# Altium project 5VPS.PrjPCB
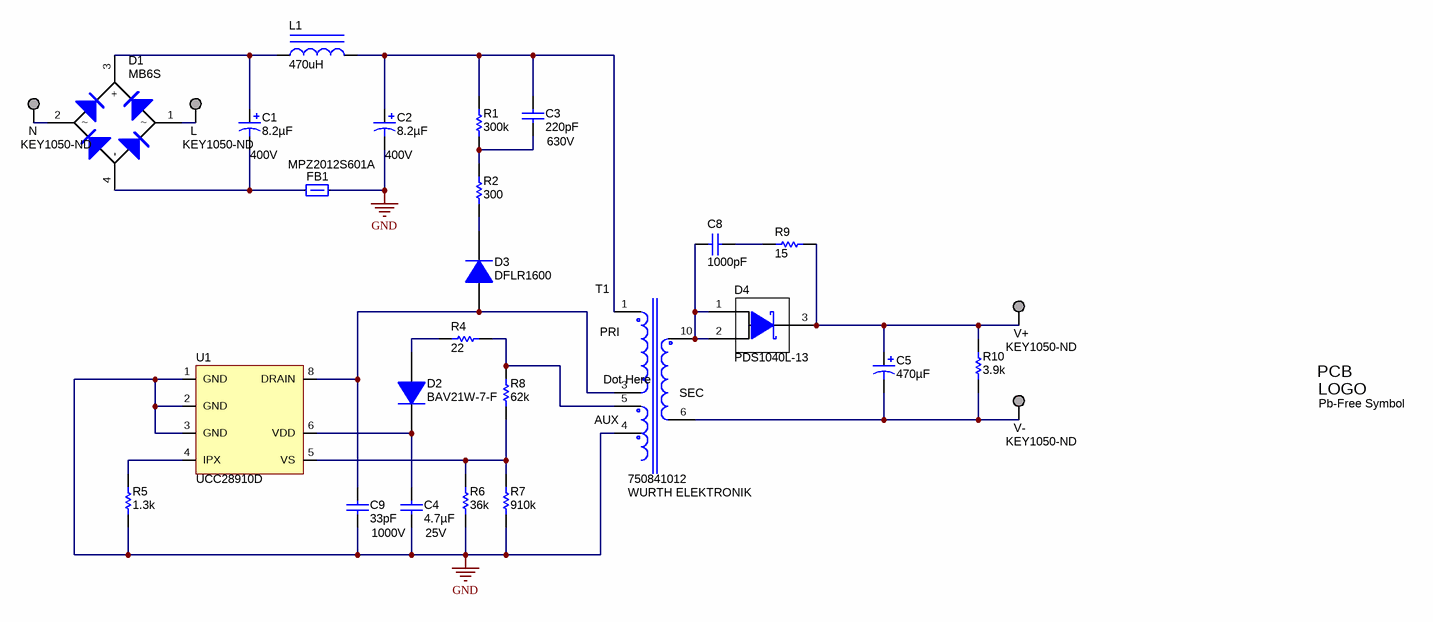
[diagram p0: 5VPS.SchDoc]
CopyrightYear: 2014; PCB_Layout: Mars Leung; PCB_Rev: E1; PRJ_Customer: Public Release; PRJ_Engineer: Mars Leung; PRJ_Number: TIDC-WIFI-METER-READING; PRJ_Title: UCC28910 5V 5W; SCH_Rev: E1; TechSupport: http://www.ti.com/support
1 sheet, 29 parts. Net scope: global (net labels, ports and power ports of the same name join across sheets).
Board file: 5VPS.PcbDoc

## Sheet 5VPS.SchDoc: TIDC-WIFI-METER-READING
size 431 x 279 mm; Date: Not shown in title block; ApprovedBy: Not shown in title block; CheckedBy: Not shown in title block; Author: Not shown in title block; CompanyName: Not shown in title block; Engineer: Not shown in title block; Organization: Not shown in title block; Address1: Not shown in title block; Address2: Not shown in title block; Address3: Not shown in title block; Address4: Not shown in title block; DocumentNumber: 1; Revision: Use project parameter SCH_Rev; SheetNumber: 1; SheetTotal: 1; PageSetup: Record=PageOptions¦CenterHorizontal=True¦CenterVertical=True¦PrintScale=0.64¦XCorrection=1.00¦YCorrection=1.00¦PrintKind=0¦BorderSize=5000000¦LeftOffset=0¦BottomOffset=0¦Orientation=2¦PaperLength=1000¦PaperWidth=1000¦Scale=100¦PaperSource=15¦PrintQuality=600¦MediaType=1¦DitherType=10¦PaperKind=Letter¦PrintScaleMode=1

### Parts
C1  ValueDisplayed: 8.2µF  Value2: 400V  [CAPPRD350W60D800H1100]  (hidden comment: 400AX8.2M8X16)
C2  ValueDisplayed: 8.2µF  Value2: 400V  [CAPPRD350W60D800H1100]  (hidden comment: 400AX8.2M8X16)
C3  ValueDisplayed: 220pF  Value2: 630V  [1206]  (hidden comment: GRM31A7U2J221JW31D)
C4  ValueDisplayed: 4.7µF  Value2: 25V  [0805_HV]  (hidden comment: GRM21BC81E475KA12L)
C5  ValueDisplayed: 470µF  [7343-43]  (hidden comment: TPSE477K010R0045)
C8  ValueDisplayed: 1000pF  [0603]  (hidden comment: C1608C0G1H102J)
C9  ValueDisplayed: 33pF  Value2: 1000V  [1206]  (hidden comment: GRM31A7U3A330JW31D)
D1  MB6S  [TO-269AA]
D2  BAV21W-7-F  [SOD-123]
D3  DFLR1600  [powerDI123]
D4  PDS1040L-13  [PowerDI5]
FB1  MPZ2012S601A  [0805_HV]
L  KEY1050-ND  [TESTPOINT]  (no BOM)
L1  470uH  [IND_WE-TI_XS]
Logo?  Pb-Free Symbol  [Pb-Free_Overlay_Small]  (no BOM)
N  KEY1050-ND  [TESTPOINT]  (no BOM)
R1  value 300k  [1206]  (hidden comment: RC1206FR-07300KL)
R2  value 300  [1206]  (hidden comment: RC1206FR-07300RL)
R4  value 22  [0603]  (hidden comment: CRCW060322R0JNEA)
R5  value 1.3k  [0603]  (hidden comment: RC0603JR-071K3L)
R6  value 36k  [0603]  (hidden comment: CRCW060336K0JNEA)
R7  value 910k  [0603]  (hidden comment: CRCW0603910KJNEA)
R8  value 62k  [0805]  (hidden comment: CRCW080562K0JNEA)
R9  value 15  [0805_HV]  (hidden comment: ERJ-6GEYJ150V)
R10  value 3.9k  [0603]  (hidden comment: RC0603JR-073K9L)
T1  750841012  Manufacturer: WURTH ELEKTRONIK  [TF-1613(EE-16)]
U1  UCC28910D  [D0007A_N]
V+  KEY1050-ND  [TESTPOINT]  (no BOM)
V-  KEY1050-ND  [TESTPOINT]  (no BOM)

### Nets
GND: C2.2(-) C4.2 C9.2 FB1.2 R5.1 R6.1 R7.1 T1.4 U1.1(GND) U1.2(GND) U1.3(GND)
NetC1_1: C1.1(+) D1.3(+) L1.1
NetC1_2: C1.2(-) D1.4(-) FB1.1
NetC2_1: C2.1(+) C3.1 L1.2 R1.1 T1.1
NetC3_2: C3.2 R1.2 R2.2
NetC4_1: C4.1 D2.1(K) U1.6(VDD)
NetC5_1: C5.1(+) D4.3(K) R9.2 R10.2 V+.1
NetC5_2: C5.2(-) R10.1 T1.6 V-.1
NetC8_1: C8.1 R9.1
NetC8_2: C8.2 D4.1(A) D4.2(A) T1.10
NetC9_1: C9.1 D3.2(A) T1.3 U1.8(DRAIN)
NetD1_1: D1.1 L.1
NetD1_2: D1.2 N.1
NetD2_2: D2.2(A) R4.1
NetD3_1: D3.1(K) R2.1
NetR4_2: R4.2 R8.2 T1.5
NetR5_2: R5.2 U1.4(IPX)
NetR6_2: R6.2 R7.2 R8.1 U1.5(VS)

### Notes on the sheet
- (near T1) Dot Here

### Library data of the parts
C1 C2 = 400AX6R8M8x11: CAP, AL, 6.8uF, 400V, +/-20%, TH; Manufacturer: Rubycon; Polarized: Y; CompType: Capacitor; Value: 8.2uF; U/M: EA; Cap_F: 0.0000082; Tolerance_%: 20; Value1: Unknown; VDC_V: 400; TaMin_C: -40; TaMax_C: 105; Cap_Case: 8x16
C3 = GRM31A7U2J221JW31D: CAP, CERM, 220pF, 630V, +/-5%, U2J, 1206; Manufacturer: MuRata; Polarized: N; CompType: Capacitor; U/M: EA; Cap_F: 0.00000000022; Tolerance_%: 5; Value1: Unknown; VDC_V: 630; TaMin_C: -55; TaMax_C: 125
C4 = GRM21BC81E475KA12L: CAP, CERM, 4.7uF, 25V, +/-10%, X6S, 0805; Manufacturer: MuRata; Polarized: N; CompType: Capacitor; U/M: EA; Cap_F: 0.0000047; Tolerance_%: 10; Value1: Unknown; VDC_V: 25; TaMin_C: -55; TaMax_C: 105; Cap_Case: 0805
C5 = TPSE477K010R0045: CAP, TA, 470uF, 10V, +/-10%, 0.045 ohm, SMD; Manufacturer: AVX; Polarized: Y; CompType: Capacitor; U/M: EA; Cap_F: 0.00047; Tolerance_%: 10; ESR_Ohm: 0.045; IRMS_A: 1.723; TaMin_C: -55; TaMax_C: 125; Cap_Case: E
C8 = C1608C0G1H102J: CAP, CERM, 1000pF, 50V, +/-5%, C0G/NP0, 0603; Manufacturer: TDK; Polarized: N; CompType: Capacitor; U/M: EA; Cap_F: 0.000000001; Tolerance_%: 5; ESR_Ohm: 0.0563; Value1: 0.0563 ohm; VDC_V: 50; TaMin_C: -55; TaMax_C: 125
C9 = GRM31A7U3A331JW31D: CAP, CERM, 33pF, 1000V, +/-5%, U2J, 1206; Manufacturer: MuRata; Polarized: N; CompType: Capacitor; U/M: EA; Cap_F: 0.00000000033; Tolerance_%: 5; Value1: Unknown; VDC_V: 1000; TaMin_C: -55; TaMax_C: 125
D1 = MB1S: Diode, Switching-Bridge, 100V, 0.5A, SOIC-4; Manufacturer: Fairchild Semiconductor; SymbolCreator: a0411947; U/M: EA; Vf_V: 1; Value: 600V; Value2: 1V; Io_A: 0.5; Vr_V: 100; TJmax_C: 150
D2 = BAV21W-7-F: Diode, Switching, 200V, 0.2A, SOD-123; Manufacturer: Diodes Inc.; U/M: EA; Vf_V: 1.25; Value2: 1.25V; Io_A: 0.2; Vr_V: 200; TJmax_C: 150
D3 = DFLU1400-7: Diode, Superfast Rectifier, 600V, 1A, PowerDI123; Manufacturer: Diodes Inc.; U/M: EA; Vf_V: 1.25; Value2: 1.25V; Io_A: 1; Vr_V: 400; TJmax_C: 150; RJC_CperW: 117
D4 = PDS1040L-13: Diode, Schottky, 40V, 10A, PowerDI5; Manufacturer: Diodes Inc.; U/M: EA; Vf_V: 0.49; Value2: 0.49V; Io_A: 10; Vr_V: 40; TJmax_C: 150; RJC_CperW: 85
FB1 = MPZ2012S601A: 2A Ferrite Bead, 600 ohm @ 100MHz, SMD; Manufacturer: TDK; Value: 600 ohm; Imax_A: 2; DCR_ohm: 0.1; Value1: 0.1 ohm; ZTyp@100MHz_Ohm: 600; U/M: EA
L N V+ V- = TESTPOINT: TEST POINT.  No entry in BOM.
L1 = 7447462471: Inductor, Unshielded Drum Core, Ferrite, 470uH, 0.35A, 1.58 ohm, TH; Manufacturer: Wurth Elektronik eiSos; Ind_H: 470.0E-6; ValueDisplayed: 470µH; Imax_A: 0.35; Irms: 0.35A @ 40C rise; Isat: 0.4A @ 10% inductance drop; DCR_ohm: 1.58; U/M: EA
Logo? = Pb-Free: SymbolCreator: a0412235
R1 = RC1206FR-07300KL: RES, 300k ohm, 1%, 0.25W, 1206; Manufacturer: Yageo America; CompType: Resistor; Res_ohm: 300000; Tolerance_%: 1; Power_W: 0.25; VDC_V: 200; TempCo: 100 ppm/C; U/M: EA
R2 = RC1206FR-07300RL: RES, 300 ohm, 1%, 0.25W, 1206; Manufacturer: Yageo America; CompType: Resistor; Value_Code: 300R; Tolerance_%: 1; Power_W: 0.25; VDC_V: 200; TempCo: 100 ppm/C; U/M: EA
R4 = CRCW060322R0JNEA: RES, 22 ohm, 5%, 0.1W, 0603; Manufacturer: Vishay-Dale; CompType: Resistor; Value_Code: 22R0; Tolerance_%: 5; Power_W: 0.1; VDC_V: 75; TempCo: 200 ppm/C; EIA_Code: E24; U/M: EA
R5 = RC0603JR-071K3L: RES, 1.3k ohm, 5%, 0.1W, 0603; Manufacturer: Yageo America; CompType: Resistor; Res_ohm: 1300; Value_Code: 1k30; Tolerance_%: 5; Power_W: 0.1; VDC_V: 50; TempCo: 100 ppm/C; EIA_Code: E24; U/M: EA
R6 = CRCW060336K0JNEA: RES, 36k ohm, 5%, 0.1W, 0603; Manufacturer: Vishay-Dale; CompType: Resistor; Res_ohm: 36000; Value_Code: 36k0; Tolerance_%: 5; Power_W: 0.1; VDC_V: 75; TempCo: 200 ppm/C; EIA_Code: E24; U/M: EA
R7 = CRCW0603910KJNEA: RES, 910k ohm, 5%, 0.1W, 0603; Manufacturer: Vishay-Dale; CompType: Resistor; Res_ohm: 910000; Tolerance_%: 5; Power_W: 0.1; VDC_V: 75; TempCo: 200 ppm/C; EIA_Code: E24; U/M: EA
R8 = CRCW080562K0JNEA: RES, 62k ohm, 5%, 0.125W, 0805; Manufacturer: Vishay-Dale; CompType: Resistor; Res_ohm: 62000; Value_Code: 62k0; Tolerance_%: 5; Power_W: 0.125; VDC_V: 150; TempCo: 200 ppm/C; EIA_Code: E24; U/M: EA
R9 = ERJ-6GEYJ150V: RES, 15 ohm, 5%, 0.125W, 0805; Manufacturer: Panasonic; CompType: Resistor; Value_Code: 15R0; Tolerance_%: 5; Power_W: 0.125; VDC_V: 150; TempCo: 200 ppm/C; EIA_Code: E24; U/M: EA
R10 = RC0603JR-073K9L: RES, 3.9k ohm, 5%, 0.1W, 0603; Manufacturer: Yageo America; CompType: Resistor; Res_ohm: 3900; Value_Code: 3k90; Tolerance_%: 5; Power_W: 0.1; VDC_V: 50; TempCo: 100 ppm/C; EIA_Code: E24; U/M: EA
T1 = TF-1613(EE-16): SymbolVersion: 1.0; SymbolCreator: A0283112; CompType: Transformer; U/M: EA, IN, or GM
U1 = UCC28910D: LOW STAND-BY POWER, CV / CC PWM HV SWITCHER WITH PRIMARY SIDE REGULATION, D0007A; Alternate Manufacturer: None; Manufacturer: Texas Instruments; SymbolCreator: a0412235; CompType: IC; U/M: EA

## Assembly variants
001: not fitted FID1 FID2 FID3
